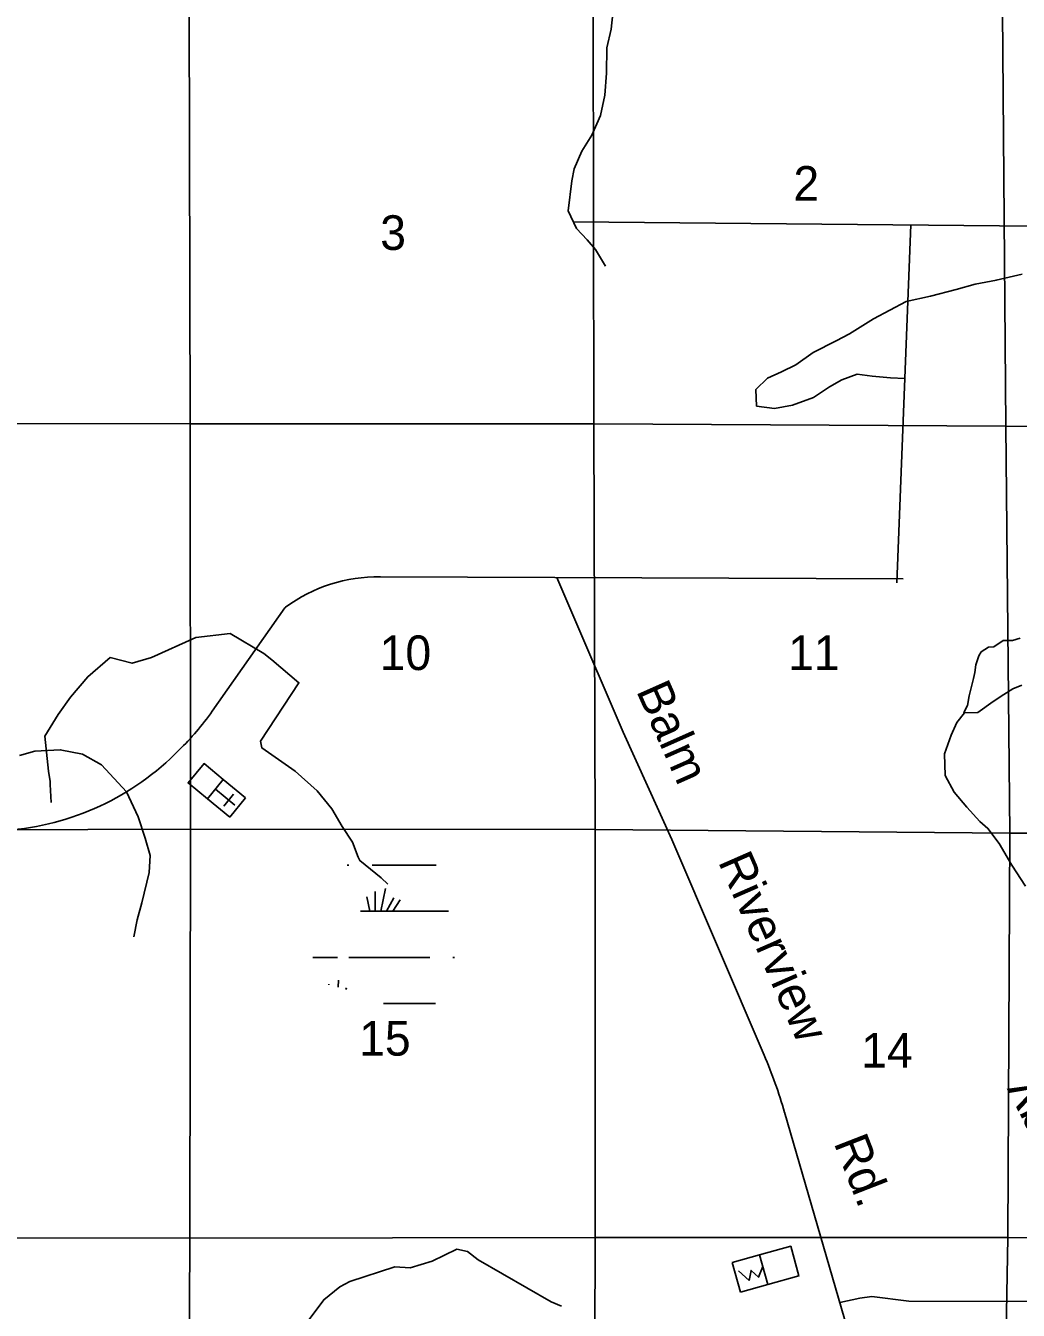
# Model space of a CAD drawing. Extents: x 380424 to 701066, y 1117407 to 1412949.
# Drawn here: x 556402 to 569307, y 1251027 to 1267730 of the extents above; entities that cross this region are included whole.
import ezdxf

# ---------------------------------------------------------------- set-up
doc = ezdxf.new("R2010")
doc.units = 0
for name, color, linetype in [('Culture', 7, 'Continuous'), ('Lakes and Ponds', 7, 'Continuous'), ('Local Roads Improved', 7, 'Continuous'), ('Local Roads Paved', 7, 'Continuous'), ('Local Roads Related Text', 7, 'Continuous'), ('Narrow Canals', 7, 'Continuous'), ('Narrow River Creek and Branch and Slough', 7, 'Continuous'), ('Narrow River Creek and Branch and Slough Text', 7, 'Continuous'), ('Section Lines', 7, 'Continuous'), ('Section Numbers', 7, 'Continuous'), ('Swamps', 7, 'Continuous')]:
    doc.layers.add(name, color=color, linetype=linetype)

msp = doc.modelspace()

# ---------------------------------------------------------------- linework, layer by layer
at = {"layer": 'Culture'}
for p, q in [((558971, 1257928), (558764, 1257677)), ((558868, 1257803), (559119, 1257596)), ((559260, 1257690), (558971, 1257928)), ((558764, 1257677), (559054, 1257439)), ((559105, 1257737), (558978, 1257582)), ((559054, 1257439), (559260, 1257690)), ((565587, 1251650), (565944, 1251748)), ((565693, 1251264), (565587, 1251650)), ((565944, 1251748), (566050, 1251362)), ((566050, 1251362), (565693, 1251264))]:
    msp.add_line(p, q, dxfattribs=at)
for points in [[(558971, 1257928), (558764, 1257677), (558513, 1257884), (558720, 1258135)], [(566050, 1251362), (565944, 1251748), (566348, 1251859), (566454, 1251473)]]:
    msp.add_lwpolyline(points, close=True, dxfattribs=at)
msp.add_lwpolyline([(565985, 1251598), (565927, 1251457), (565832, 1251546), (565807, 1251415), (565669, 1251538)], dxfattribs=at)
at = {"layer": 'Lakes and Ponds'}
msp.add_lwpolyline([(569330, 1259766), (569230, 1259734), (569111, 1259737), (568989, 1259655), (568921, 1259650), (568826, 1259587), (568795, 1259535), (568753, 1259419), (568742, 1259319), (568726, 1259241), (568669, 1259015), (568648, 1258889), (568632, 1258868), (568600, 1258794), (568779, 1258799), (568978, 1258941), (569120, 1259036), (569236, 1259109), (569351, 1259157)], dxfattribs=at)
at = {"layer": 'Local Roads Improved'}
msp.add_lwpolyline([(566986, 1251128), (567245, 1251183), (567404, 1251208), (567882, 1251147), (571149, 1251135), (571663, 1251110), (572850, 1251098)], dxfattribs=at)
at = {"layer": 'Local Roads Paved'}
for p, q in [((561014, 1260563), (567810, 1260538)), ((566269, 1253601), (567614, 1248966))]:
    msp.add_line(p, q, dxfattribs=at)
for points in [[(563308, 1260555), (563504, 1260101), (564169, 1258544), (564802, 1257148), (566002, 1254346)], [(558828, 1258816), (559769, 1260159), (559781, 1260168)]]:
    msp.add_lwpolyline(points, dxfattribs=at)
for centre, radius, start, end in [((560975, 1258559), 2004, 88.9107, 126.5966), ((556004, 1260794), 3447, 313.9099, 324.9874), ((555893, 1260758), 3500, 274.1588, 315.6267), ((560041, 1251793), 6485, 16.1855, 23.1831)]:
    msp.add_arc(centre, radius, start, end, dxfattribs=at)
at = {"layer": 'Narrow Canals'}
for points in [[(563523, 1265178), (569522, 1265125)], [(567911, 1265139), (567727, 1260484)], [(569358, 1264501), (569017, 1264422), (569022, 1264422), (568744, 1264369), (568497, 1264301), (568166, 1264212), (567851, 1264144), (567426, 1263918), (567111, 1263724), (566938, 1263634), (566639, 1263482), (566413, 1263319), (566229, 1263230), (566045, 1263146), (565893, 1262999), (565904, 1262784), (566135, 1262752), (566371, 1262794), (566644, 1262894), (566854, 1263036), (567011, 1263125), (567211, 1263199), (567405, 1263172), (567647, 1263151), (567832, 1263141)]]:
    msp.add_lwpolyline(points, dxfattribs=at)
at = {"layer": 'Narrow River Creek and Branch and Slough'}
for points in [[(564036, 1267891), (564015, 1267686), (563958, 1267444), (563952, 1267113), (563931, 1266825), (563874, 1266562), (563763, 1266305), (563632, 1266100), (563532, 1265869), (563501, 1265712), (563454, 1265323), (563564, 1265092), (563700, 1264945), (563811, 1264819), (563942, 1264604)], [(561109, 1256568), (561023, 1256652), (560748, 1256874), (560726, 1256919), (560651, 1257113), (560516, 1257316), (560380, 1257549), (560193, 1257782), (559904, 1258035), (559472, 1258340), (559453, 1258428), (559953, 1259186), (559600, 1259486), (559497, 1259569), (559059, 1259829), (558615, 1259775), (558038, 1259513), (557785, 1259440), (557499, 1259513), (557208, 1259265), (556985, 1258999), (556825, 1258775), (556650, 1258494), (556699, 1258038), (556718, 1257902), (556722, 1257864), (556733, 1257630)], [(568609, 1258794), (568507, 1258668), (568433, 1258506), (568349, 1258264), (568354, 1257980), (568475, 1257765), (568638, 1257571), (568806, 1257382), (568911, 1257293), (569058, 1257098), (569221, 1256815), (569399, 1256542)], [(556320, 1258241), (556520, 1258299), (556850, 1258315), (557139, 1258257), (557386, 1258121), (557713, 1257767), (557864, 1257443), (557953, 1257165), (558021, 1256939), (558005, 1256719), (557911, 1256325), (557853, 1256104), (557807, 1255883)], [(560035, 1250836), (560276, 1251163), (560485, 1251332), (560617, 1251402), (561199, 1251591), (561400, 1251580), (561687, 1251666), (562006, 1251820), (562144, 1251790), (562284, 1251681), (563235, 1251138), (563366, 1251080)]]:
    msp.add_lwpolyline(points, dxfattribs=at)
at = {"layer": 'Section Lines'}
for points in [[(558527, 1267958), (558539, 1262555), (553219, 1262559), (553238, 1267967)], [(563780, 1267964), (563790, 1262553), (558539, 1262555), (558527, 1267958)], [(569102, 1267920), (569146, 1262523), (563790, 1262553), (563780, 1267964)], [(574445, 1267880), (574395, 1262454), (569146, 1262523), (569102, 1267920)], [(558539, 1262555), (558545, 1257284), (553207, 1257264), (553219, 1262559)], [(563790, 1262553), (563807, 1257278), (558545, 1257284), (558539, 1262555)], [(569146, 1262523), (569197, 1257229), (563807, 1257278), (563790, 1262553)], [(574395, 1262454), (574451, 1257229), (569197, 1257229), (569146, 1262523)], [(558545, 1257284), (558537, 1251965), (553221, 1251968), (553207, 1257264)], [(563807, 1257278), (563805, 1251973), (558537, 1251965), (558545, 1257284)], [(569197, 1257229), (569170, 1251972), (563805, 1251973), (563807, 1257278)], [(574451, 1257229), (574368, 1251922), (569170, 1251972), (569197, 1257229)], [(558537, 1251965), (558509, 1246611), (553202, 1246611), (553221, 1251961), (553221, 1251968)], [(563805, 1251973), (563787, 1246629), (558509, 1246611), (558537, 1251965)], [(569170, 1251972), (569075, 1246603), (563787, 1246629), (563805, 1251973)], [(574368, 1251922), (574377, 1246747), (574380, 1246725), (569075, 1246603), (569170, 1251972)]]:
    msp.add_lwpolyline(points, close=True, dxfattribs=at)
at = {"layer": 'Swamps'}
for p, q in [((560946, 1256474), (560946, 1256216)), ((561079, 1256511), (561020, 1256216)), ((560837, 1256402), (560874, 1256216)), ((561187, 1256390), (561093, 1256215)), ((561272, 1256366), (561173, 1256217)), ((560155, 1255616), (560455, 1255616)), ((560605, 1255616), (561655, 1255616))]:
    msp.add_line(p, q, dxfattribs=at)
for points in [[(560581, 1256816), (560605, 1256816)], [(560905, 1256816), (561738, 1256816)], [(560755, 1256216), (561898, 1256216)], [(560136, 1255616), (560155, 1255616)], [(561955, 1255616), (561975, 1255616)], [(560465, 1255229), (560467, 1255319)], [(560345, 1255258), (560343, 1255269)], [(560566, 1255197), (560571, 1255221)], [(561055, 1255016), (561729, 1255016)]]:
    msp.add_lwpolyline(points, dxfattribs=at)

# ---------------------------------------------------------------- texts
at = {"layer": 'Local Roads Related Text'}
for s, rotation, p in [('Balm', 293.9625, (564334, 1259084)), ('Riverview', 293.6782, (565399, 1256863)), ('Rd.', 291.2777, (566903, 1253207))]:
    msp.add_text(s, height=450, rotation=rotation, dxfattribs=at).set_placement(p)
at = {"layer": 'Narrow River Creek and Branch and Slough Text'}
msp.add_text('Boggy', height=500, rotation=117.0935, dxfattribs=at).set_placement((570361, 1252395))
at = {"layer": 'Section Numbers'}
for s, p in [('2', (566383, 1265455)), ('3', (561011, 1264815)), ('10', (561004, 1259352)), ('11', (566314, 1259353)), ('15', (560737, 1254338)), ('14', (567265, 1254183))]:
    msp.add_text(s, height=450, rotation=0.0004, dxfattribs=at).set_placement(p)

doc.saveas('drawing.dxf')
